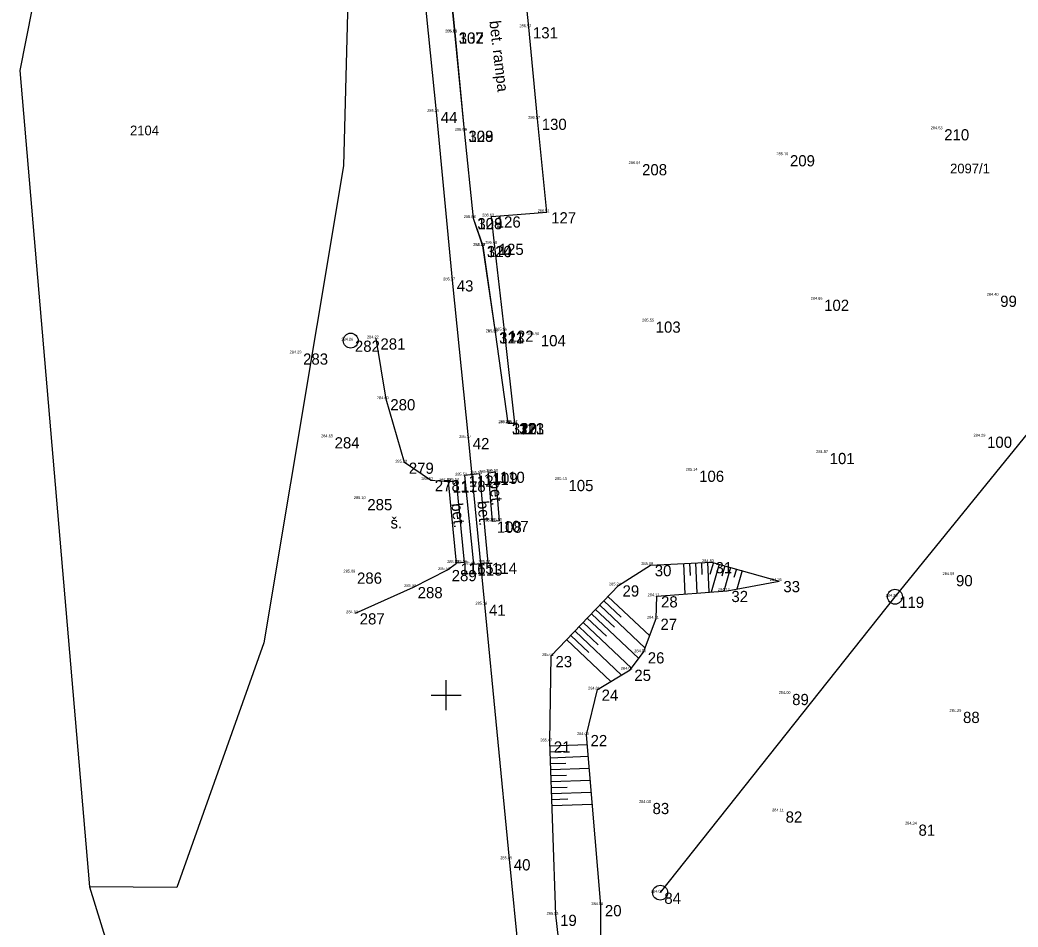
# Model space of a CAD drawing. Extents: x -594197 to -593885, y -1138044 to -1137704.
# Drawn here: x -594128.5 to -594061.7, y -1137965.5 to -1137904.8 of the extents above; entities that cross this region are included whole.
import ezdxf

# ---------------------------------------------------------------- set-up
doc = ezdxf.new("R2010")
doc.units = 0
for name, color, linetype in [('IS kanalizace', 7, 'Continuous'), ('IS neurčené', 7, 'Continuous'), ('Katastrální mapa', 7, 'Continuous'), ('Podrobný bod', 7, 'Continuous'), ('Podrobný bod výška', 7, 'Continuous'), ('Podrobný bod číslo', 7, 'Continuous'), ('Polohopisné prvky', 7, 'Continuous'), ('Popisy', 7, 'Continuous'), ('Rozhraní ploch', 7, 'Continuous'), ('Výškopis', 7, 'Continuous'), ('Výškopis šrafy', 7, 'Continuous'), ('Čtvercová síť', 7, 'Continuous')]:
    doc.layers.add(name, color=color, linetype=linetype)

msp = doc.modelspace()

# ---------------------------------------------------------------- linework, layer by layer
at = {"layer": 'IS kanalizace'}
msp.add_lwpolyline([(-594038.81, -1137904.8), (-594053.4, -1137923.01), (-594069.95, -1137943.4), (-594085.67, -1137963.22)], dxfattribs=at)
at = {"layer": 'IS neurčené'}
for centre in [(-594106.39, -1137926.25), (-594069.95, -1137943.4), (-594085.67, -1137963.22)]:
    msp.add_circle(centre, 0.5, dxfattribs=at)
at = {"layer": 'Katastrální mapa'}
for points in [[(-594122.72, -1137859.34), (-594120.63, -1137880.3), (-594122.39, -1137886.83), (-594125.63, -1137893.36), (-594128.54, -1137908.17), (-594123.89, -1137962.84)], [(-594122.72, -1137859.34), (-594105.5, -1137861.68), (-594106.87, -1137914.54), (-594112.21, -1137946.48), (-594118.04, -1137962.87), (-594123.89, -1137962.84)], [(-594123.89, -1137962.84), (-594119.16, -1137978.15), (-594107.44, -1137982.65), (-594107.86, -1137987.33)]]:
    msp.add_lwpolyline(points, dxfattribs=at)
at = {"layer": 'Podrobný bod'}
for p, q in [((-594099.44, -1137905.61), (-594099.44, -1137905.61)), ((-594099.43, -1137905.61), (-594099.43, -1137905.61)), ((-594094.47, -1137905.26), (-594094.47, -1137905.26)), ((-594100.64, -1137910.93), (-594100.64, -1137910.93)), ((-594093.88, -1137911.39), (-594093.88, -1137911.39)), ((-594098.79, -1137912.19), (-594098.79, -1137912.19)), ((-594098.79, -1137912.19), (-594098.79, -1137912.19)), ((-594066.93, -1137912.09), (-594066.93, -1137912.09)), ((-594077.26, -1137913.83), (-594077.26, -1137913.83)), ((-594087.16, -1137914.43), (-594087.16, -1137914.43)), ((-594093.25, -1137917.65), (-594093.25, -1137917.65)), ((-594098.19, -1137918.04), (-594098.19, -1137918.04)), ((-594098.19, -1137918.04), (-594098.19, -1137918.04)), ((-594096.96, -1137917.93), (-594096.96, -1137917.93)), ((-594096.76, -1137919.76), (-594096.76, -1137919.76)), ((-594097.56, -1137919.91), (-594097.56, -1137919.91)), ((-594097.55, -1137919.91), (-594097.55, -1137919.91)), ((-594099.57, -1137922.21), (-594099.57, -1137922.21)), ((-594074.97, -1137923.51), (-594074.97, -1137923.51)), ((-594063.18, -1137923.24), (-594063.18, -1137923.24)), ((-594086.25, -1137924.97), (-594086.25, -1137924.97)), ((-594096.73, -1137925.69), (-594096.73, -1137925.69)), ((-594096.72, -1137925.69), (-594096.72, -1137925.69)), ((-594096.1, -1137925.58), (-594096.1, -1137925.58)), ((-594093.94, -1137925.88), (-594093.94, -1137925.88)), ((-594106.39, -1137926.25), (-594106.39, -1137926.25)), ((-594104.68, -1137926.1), (-594104.68, -1137926.1)), ((-594109.86, -1137927.11), (-594109.86, -1137927.11)), ((-594104.02, -1137930.17), (-594104.02, -1137930.17)), ((-594095.88, -1137931.78), (-594095.88, -1137931.78)), ((-594095.87, -1137931.77), (-594095.87, -1137931.77)), ((-594095.4, -1137931.77), (-594095.4, -1137931.77)), ((-594095.39, -1137931.78), (-594095.39, -1137931.78)), ((-594107.75, -1137932.72), (-594107.75, -1137932.72)), ((-594098.5, -1137932.77), (-594098.5, -1137932.77)), ((-594064.06, -1137932.68), (-594064.06, -1137932.68)), ((-594074.6, -1137933.77), (-594074.6, -1137933.77)), ((-594102.78, -1137934.42), (-594102.78, -1137934.42)), ((-594097.76, -1137935.18), (-594097.76, -1137935.18)), ((-594097.16, -1137935.1), (-594097.16, -1137935.1)), ((-594096.69, -1137935.03), (-594096.69, -1137935.03)), ((-594083.34, -1137934.96), (-594083.34, -1137934.96)), ((-594101.04, -1137935.59), (-594101.04, -1137935.59)), ((-594099.85, -1137935.68), (-594099.85, -1137935.68)), ((-594099.31, -1137935.63), (-594099.31, -1137935.63)), ((-594098.77, -1137935.29), (-594098.77, -1137935.29)), ((-594092.09, -1137935.58), (-594092.09, -1137935.58)), ((-594105.56, -1137936.86), (-594105.56, -1137936.86)), ((-594096.89, -1137938.37), (-594096.89, -1137938.37)), ((-594096.43, -1137938.32), (-594096.43, -1137938.32)), ((-594099.31, -1137941.15), (-594099.31, -1137941.15)), ((-594098.78, -1137941.12), (-594098.78, -1137941.12)), ((-594098.18, -1137941.23), (-594098.18, -1137941.23)), ((-594097.21, -1137941.13), (-594097.21, -1137941.13)), ((-594086.31, -1137941.28), (-594086.31, -1137941.28)), ((-594082.24, -1137941.08), (-594082.24, -1137941.08)), ((-594106.25, -1137941.78), (-594106.25, -1137941.78)), ((-594099.91, -1137941.61), (-594099.91, -1137941.61)), ((-594077.7, -1137942.35), (-594077.7, -1137942.35)), ((-594066.14, -1137941.95), (-594066.14, -1137941.95)), ((-594102.19, -1137942.75), (-594102.19, -1137942.75)), ((-594088.47, -1137942.64), (-594088.47, -1137942.64)), ((-594081.18, -1137943.01), (-594081.18, -1137943.01)), ((-594097.41, -1137943.93), (-594097.41, -1137943.93)), ((-594085.89, -1137943.37), (-594085.89, -1137943.37)), ((-594069.95, -1137943.4), (-594069.95, -1137943.4)), ((-594106.07, -1137944.51), (-594106.07, -1137944.51)), ((-594085.93, -1137944.87), (-594085.93, -1137944.87)), ((-594086.78, -1137947.12), (-594086.78, -1137947.12)), ((-594092.96, -1137947.37), (-594092.96, -1137947.37)), ((-594087.68, -1137948.29), (-594087.68, -1137948.29)), ((-594089.87, -1137949.62), (-594089.87, -1137949.62)), ((-594077.11, -1137949.91), (-594077.11, -1137949.91)), ((-594065.67, -1137951.11), (-594065.67, -1137951.11)), ((-594093.07, -1137953.09), (-594093.07, -1137953.09)), ((-594090.61, -1137952.66), (-594090.61, -1137952.66)), ((-594086.46, -1137957.21), (-594086.46, -1137957.21)), ((-594077.55, -1137957.78), (-594077.55, -1137957.78)), ((-594068.65, -1137958.66), (-594068.65, -1137958.66)), ((-594095.75, -1137960.98), (-594095.75, -1137960.98)), ((-594085.67, -1137963.22), (-594085.67, -1137963.22)), ((-594089.65, -1137964.05), (-594089.65, -1137964.05)), ((-594092.65, -1137964.7), (-594092.65, -1137964.7))]:
    msp.add_line(p, q, dxfattribs=at)
at = {"layer": 'Polohopisné prvky'}
msp.add_lwpolyline([(-594101.45, -1137867.17), (-594103.25, -1137867.33), (-594102.56, -1137874.38), (-594101.92, -1137880.59), (-594101.3, -1137886.85), (-594100.65, -1137893.31), (-594100.07, -1137899.21), (-594099.43, -1137905.61), (-594098.79, -1137912.19), (-594098.19, -1137918.04), (-594097.55, -1137919.91), (-594096.72, -1137925.69), (-594095.87, -1137931.77)], dxfattribs=at)
at = {"layer": 'Rozhraní ploch'}
for points in [[(-594098.37, -1138025.23), (-594097.42, -1138020.88), (-594096.44, -1138015.16), (-594095.71, -1138009.9), (-594095.18, -1138005.26), (-594094.63, -1137998.75), (-594094.37, -1137992.38), (-594094.32, -1137983.2), (-594094.65, -1137973.95), (-594095.11, -1137967.54), (-594095.75, -1137960.98), (-594097.41, -1137943.93), (-594098.5, -1137932.77), (-594099.57, -1137922.21), (-594100.64, -1137910.93), (-594102.1, -1137896.65), (-594103.58, -1137881.21), (-594104.68, -1137869.94), (-594106.08, -1137856.13)], [(-594103.26, -1137867.32), (-594102.57, -1137874.38), (-594101.92, -1137880.59), (-594101.32, -1137886.85), (-594100.66, -1137893.31), (-594100.08, -1137899.21), (-594099.44, -1137905.61), (-594098.79, -1137912.19), (-594098.19, -1137918.04), (-594097.56, -1137919.91), (-594096.73, -1137925.69), (-594095.88, -1137931.78), (-594095.87, -1137931.77)], [(-594095.87, -1137931.77), (-594095.4, -1137931.77), (-594096.1, -1137925.58), (-594096.76, -1137919.76), (-594096.96, -1137917.93), (-594093.25, -1137917.65), (-594093.88, -1137911.39), (-594094.47, -1137905.26), (-594095.14, -1137898.78), (-594095.71, -1137892.85), (-594096.35, -1137886.34), (-594096.98, -1137879.98), (-594097.29, -1137877.12), (-594091.33, -1137876.27), (-594085.77, -1137875.5), (-594079.99, -1137874.67), (-594073.96, -1137873.82), (-594067.27, -1137872.88), (-594061.95, -1137872.11), (-594056.14, -1137871.3)], [(-594101.04, -1137935.59), (-594102.78, -1137934.42), (-594104.02, -1137930.17), (-594104.68, -1137926.1)], [(-594097.76, -1137935.18), (-594098.77, -1137935.29), (-594098.18, -1137941.23), (-594097.21, -1137941.13)], [(-594097.76, -1137935.18), (-594097.21, -1137941.13)], [(-594096.43, -1137938.32), (-594096.89, -1137938.37), (-594097.16, -1137935.1), (-594096.69, -1137935.03)], [(-594096.43, -1137938.32), (-594096.69, -1137935.03)], [(-594101.04, -1137935.59), (-594099.85, -1137935.68)], [(-594098.78, -1137941.12), (-594099.31, -1137941.15), (-594099.85, -1137935.68), (-594099.31, -1137935.63)], [(-594098.78, -1137941.12), (-594099.31, -1137935.63)], [(-594099.91, -1137941.61), (-594099.31, -1137941.15)], [(-594106.07, -1137944.51), (-594102.19, -1137942.75), (-594099.91, -1137941.61)]]:
    msp.add_lwpolyline(points, dxfattribs=at)
at = {"layer": 'Výškopis'}
for points in [[(-594094.03, -1138016.09), (-594092.75, -1138008.99), (-594092.58, -1138001.81), (-594092.32, -1137993.06), (-594092.21, -1137989.19), (-594091.4, -1137988.94), (-594091.29, -1137982.78), (-594091.71, -1137972.89), (-594092.65, -1137964.7), (-594093.07, -1137953.09), (-594092.96, -1137947.37), (-594088.47, -1137942.64), (-594086.31, -1137941.28), (-594082.24, -1137941.08), (-594077.7, -1137942.35)], [(-594094.03, -1138016.09), (-594092.04, -1138014.73), (-594091.44, -1138009.1), (-594090.73, -1138001.94), (-594089.76, -1137993.02), (-594089.3, -1137982.65), (-594089.63, -1137972.76), (-594089.65, -1137964.05), (-594090.61, -1137952.66), (-594089.87, -1137949.62), (-594087.68, -1137948.29), (-594086.78, -1137947.12), (-594085.93, -1137944.87), (-594085.89, -1137943.37), (-594081.18, -1137943.01), (-594077.7, -1137942.35)]]:
    msp.add_lwpolyline(points, dxfattribs=at)
at = {"layer": 'Výškopis šrafy'}
for p, q in [((-594084.11, -1137941.17), (-594084.01, -1137943.23)), ((-594083.71, -1137941.15), (-594083.67, -1137941.97)), ((-594083.31, -1137941.13), (-594083.21, -1137943.17)), ((-594082.91, -1137941.11), (-594082.87, -1137941.92)), ((-594082.51, -1137941.09), (-594082.41, -1137943.1)), ((-594082.11, -1137941.12), (-594082.34, -1137941.92)), ((-594081.73, -1137941.22), (-594082.25, -1137943.09)), ((-594081.34, -1137941.33), (-594081.54, -1137942.02)), ((-594080.96, -1137941.44), (-594081.4, -1137943.03)), ((-594080.57, -1137941.55), (-594080.73, -1137942.12)), ((-594080.19, -1137941.65), (-594080.53, -1137942.89)), ((-594089.44, -1137943.67), (-594088.28, -1137944.78)), ((-594089.17, -1137943.38), (-594086.37, -1137946.03)), ((-594090.27, -1137944.54), (-594087.1, -1137947.54)), ((-594090, -1137944.25), (-594088.74, -1137945.44)), ((-594089.72, -1137943.96), (-594086.68, -1137946.85)), ((-594090.82, -1137945.12), (-594087.6, -1137948.18)), ((-594090.55, -1137944.83), (-594089.27, -1137946.04)), ((-594091.37, -1137945.7), (-594088.27, -1137948.65)), ((-594091.1, -1137945.41), (-594089.82, -1137946.62)), ((-594091.92, -1137946.28), (-594088.97, -1137949.08)), ((-594091.65, -1137945.99), (-594090.44, -1137947.14)), ((-594093.06, -1137953.39), (-594090.56, -1137953.3)), ((-594093.04, -1137953.79), (-594092.04, -1137953.75)), ((-594093.03, -1137954.19), (-594090.49, -1137954.09)), ((-594093.02, -1137954.58), (-594091.99, -1137954.55)), ((-594093, -1137954.98), (-594090.42, -1137954.89)), ((-594092.99, -1137955.38), (-594091.95, -1137955.35)), ((-594092.97, -1137955.78), (-594090.35, -1137955.69)), ((-594092.96, -1137956.18), (-594091.9, -1137956.15)), ((-594092.94, -1137956.58), (-594090.29, -1137956.49)), ((-594092.93, -1137956.98), (-594091.86, -1137956.94)), ((-594092.91, -1137957.38), (-594090.22, -1137957.29))]:
    msp.add_line(p, q, dxfattribs=at)
at = {"layer": 'Čtvercová síť'}
for p, q in [((-594100, -1137951), (-594100, -1137949)), ((-594101, -1137950), (-594099, -1137950))]:
    msp.add_line(p, q, dxfattribs=at)

# ---------------------------------------------------------------- texts
at = {"layer": 'Katastrální mapa'}
for s, p in [('2104', (-594121.17, -1137912.5)), ('2097/1', (-594066.256, -1137915.049))]:
    msp.add_text(s, height=0.65, dxfattribs=at).set_placement(p)
at = {"layer": 'Podrobný bod výška'}
for s, p in [('286.57 ', (-594095.095, -1137905.26)), ('285.35 ', (-594100.065, -1137905.61)), ('286.68 ', (-594100.055, -1137905.61)), ('285.35 ', (-594101.265, -1137910.93)), ('286.57 ', (-594094.505, -1137911.39)), ('286.69 ', (-594099.415, -1137912.19)), ('285.35 ', (-594099.415, -1137912.19)), ('284.53 ', (-594067.555, -1137912.09)), ('285.16 ', (-594077.885, -1137913.83)), ('286.04 ', (-594087.785, -1137914.43)), ('286.67 ', (-594098.815, -1137918.04)), ('285.35 ', (-594098.815, -1137918.04)), ('286.63 ', (-594097.585, -1137917.93)), ('286.51 ', (-594093.875, -1137917.65)), ('285.37 ', (-594098.185, -1137919.91)), ('286.49 ', (-594098.175, -1137919.91)), ('286.48 ', (-594097.385, -1137919.76)), ('285.37 ', (-594100.195, -1137922.21)), ('284.40 ', (-594063.805, -1137923.24)), ('284.86 ', (-594075.595, -1137923.51)), ('285.55 ', (-594086.875, -1137924.97)), ('285.37 ', (-594097.355, -1137925.69)), ('285.95 ', (-594097.345, -1137925.69)), ('285.96 ', (-594096.725, -1137925.58)), ('285.90 ', (-594094.565, -1137925.88)), ('284.26 ', (-594107.015, -1137926.25)), ('284.22 ', (-594105.305, -1137926.1)), ('284.29 ', (-594110.485, -1137927.11)), ('284.60 ', (-594104.645, -1137930.17)), ('285.37 ', (-594096.505, -1137931.78)), ('285.45 ', (-594096.495, -1137931.77)), ('285.44 ', (-594096.025, -1137931.77)), ('285.37 ', (-594096.015, -1137931.78)), ('284.65 ', (-594108.375, -1137932.72)), ('285.37 ', (-594099.125, -1137932.77)), ('284.29 ', (-594064.685, -1137932.68)), ('284.67 ', (-594075.225, -1137933.77)), ('285.28 ', (-594103.405, -1137934.42)), ('285.52 ', (-594099.395, -1137935.29)), ('285.51 ', (-594098.385, -1137935.18)), ('285.52 ', (-594097.785, -1137935.1)), ('285.50 ', (-594097.315, -1137935.03)), ('285.14 ', (-594083.965, -1137934.96)), ('285.52 ', (-594101.665, -1137935.59)), ('285.52 ', (-594100.475, -1137935.68)), ('285.52 ', (-594099.935, -1137935.63)), ('285.43 ', (-594092.715, -1137935.58)), ('285.10 ', (-594106.185, -1137936.86)), ('285.51 ', (-594097.515, -1137938.37)), ('285.50 ', (-594097.055, -1137938.32)), ('285.53 ', (-594099.935, -1137941.15)), ('285.56 ', (-594099.405, -1137941.12)), ('285.51 ', (-594098.805, -1137941.23)), ('285.52 ', (-594097.835, -1137941.13)), ('285.08 ', (-594086.935, -1137941.28)), ('284.83 ', (-594082.865, -1137941.08)), ('285.08 ', (-594106.875, -1137941.78)), ('285.51 ', (-594100.535, -1137941.61)), ('284.09 ', (-594066.765, -1137941.95)), ('285.30 ', (-594102.815, -1137942.75)), ('285.24 ', (-594089.095, -1137942.64)), ('284.26 ', (-594078.325, -1137942.35)), ('284.11 ', (-594086.515, -1137943.37)), ('284.12 ', (-594081.805, -1137943.01)), ('284.26 ', (-594070.575, -1137943.4)), ('285.39 ', (-594098.035, -1137943.93)), ('284.93 ', (-594106.695, -1137944.51)), ('284.11 ', (-594086.555, -1137944.87)), ('285.61 ', (-594093.585, -1137947.37)), ('284.00 ', (-594087.405, -1137947.12)), ('284.01 ', (-594088.305, -1137948.29)), ('284.01 ', (-594090.495, -1137949.62)), ('284.00 ', (-594077.735, -1137949.91)), ('284.25 ', (-594066.295, -1137951.11)), ('284.06 ', (-594091.235, -1137952.66)), ('285.47 ', (-594093.695, -1137953.09)), ('284.00 ', (-594087.085, -1137957.21)), ('284.11 ', (-594078.175, -1137957.78)), ('284.34 ', (-594069.275, -1137958.66)), ('285.45 ', (-594096.375, -1137960.98)), ('284.07 ', (-594086.295, -1137963.22)), ('284.08 ', (-594090.275, -1137964.05)), ('285.53 ', (-594093.275, -1137964.7))]:
    msp.add_text(s, height=0.1875, dxfattribs=at).set_placement(p)
at = {"layer": 'Podrobný bod číslo'}
for s, p in [(' 307', (-594099.44, -1137906.36)), (' 132', (-594099.43, -1137906.36)), (' 131', (-594094.47, -1137906.01)), (' 44', (-594100.64, -1137911.68)), (' 130', (-594093.88, -1137912.14)), (' 308', (-594098.79, -1137912.94)), (' 129', (-594098.79, -1137912.94)), (' 210', (-594066.93, -1137912.84)), (' 209', (-594077.26, -1137914.58)), (' 208', (-594087.16, -1137915.18)), (' 127', (-594093.25, -1137918.4)), (' 309', (-594098.19, -1137918.79)), (' 128', (-594098.19, -1137918.79)), (' 126', (-594096.96, -1137918.68)), (' 125', (-594096.76, -1137920.51)), (' 310', (-594097.56, -1137920.66)), (' 124', (-594097.55, -1137920.66)), (' 43', (-594099.57, -1137922.96)), (' 99', (-594063.18, -1137923.99)), (' 102', (-594074.97, -1137924.26)), (' 103', (-594086.25, -1137925.72)), (' 311', (-594096.73, -1137926.44)), (' 123', (-594096.72, -1137926.44)), (' 122', (-594096.1, -1137926.33)), (' 104', (-594093.94, -1137926.63)), (' 282', (-594106.39, -1137927)), (' 281', (-594104.68, -1137926.85)), (' 283', (-594109.86, -1137927.86)), (' 280', (-594104.02, -1137930.92)), (' 312', (-594095.88, -1137932.53)), (' 120', (-594095.87, -1137932.52)), (' 313', (-594095.39, -1137932.53)), (' 121', (-594095.4, -1137932.52)), (' 284', (-594107.75, -1137933.47)), (' 42', (-594098.5, -1137933.52)), (' 100', (-594064.06, -1137933.43)), (' 101', (-594074.6, -1137934.52)), (' 279', (-594102.78, -1137935.17)), (' 111', (-594097.76, -1137935.93)), (' 109', (-594097.16, -1137935.85)), (' 110', (-594096.69, -1137935.78)), (' 106', (-594083.34, -1137935.71)), (' 278', (-594101.04, -1137936.34)), (' 117', (-594099.85, -1137936.43)), (' 118', (-594099.31, -1137936.38)), (' 112', (-594098.77, -1137936.04)), (' 105', (-594092.09, -1137936.33)), (' 285', (-594105.56, -1137937.61)), (' 108', (-594096.89, -1137939.12)), (' 107', (-594096.43, -1137939.07)), (' 116', (-594099.31, -1137941.9)), (' 115', (-594098.78, -1137941.87)), (' 113', (-594098.18, -1137941.98)), (' 114', (-594097.21, -1137941.88)), (' 30', (-594086.31, -1137942.03)), (' 31', (-594082.24, -1137941.83)), (' 286', (-594106.25, -1137942.53)), (' 289', (-594099.91, -1137942.36)), (' 90', (-594066.14, -1137942.7)), (' 33', (-594077.7, -1137943.1)), (' 288', (-594102.19, -1137943.5)), (' 29', (-594088.47, -1137943.39)), (' 32', (-594081.18, -1137943.76)), (' 41', (-594097.41, -1137944.68)), (' 28', (-594085.89, -1137944.12)), (' 119', (-594069.95, -1137944.15)), (' 287', (-594106.07, -1137945.26)), (' 27', (-594085.93, -1137945.62)), (' 26', (-594086.78, -1137947.87)), (' 23', (-594092.96, -1137948.12)), (' 25', (-594087.68, -1137949.04)), (' 24', (-594089.87, -1137950.37)), (' 89', (-594077.11, -1137950.66)), (' 88', (-594065.67, -1137951.86)), (' 21', (-594093.07, -1137953.84)), (' 22', (-594090.61, -1137953.41)), (' 83', (-594086.46, -1137957.96)), (' 82', (-594077.55, -1137958.53)), (' 81', (-594068.65, -1137959.41)), (' 40', (-594095.75, -1137961.73)), (' 84', (-594085.67, -1137963.97)), (' 20', (-594089.65, -1137964.8)), (' 19', (-594092.65, -1137965.45))]:
    msp.add_text(s, height=0.75, dxfattribs=at).set_placement(p)
at = {"layer": 'Popisy'}
for s, rotation, p in [('bet. rampa', 276.65363, (-594097.11, -1137904.86)), ('bet.', 275.0509, (-594097.1, -1137935.66)), ('bet.', 276.2128, (-594099.65, -1137937.17)), ('bet.', 275.03824, (-594097.91, -1137937.01))]:
    msp.add_text(s, height=0.75, rotation=rotation, dxfattribs=at).set_placement(p)
msp.add_text('š.', height=0.75, dxfattribs=at).set_placement((-594103.73, -1137938.83))

doc.saveas('drawing.dxf')
